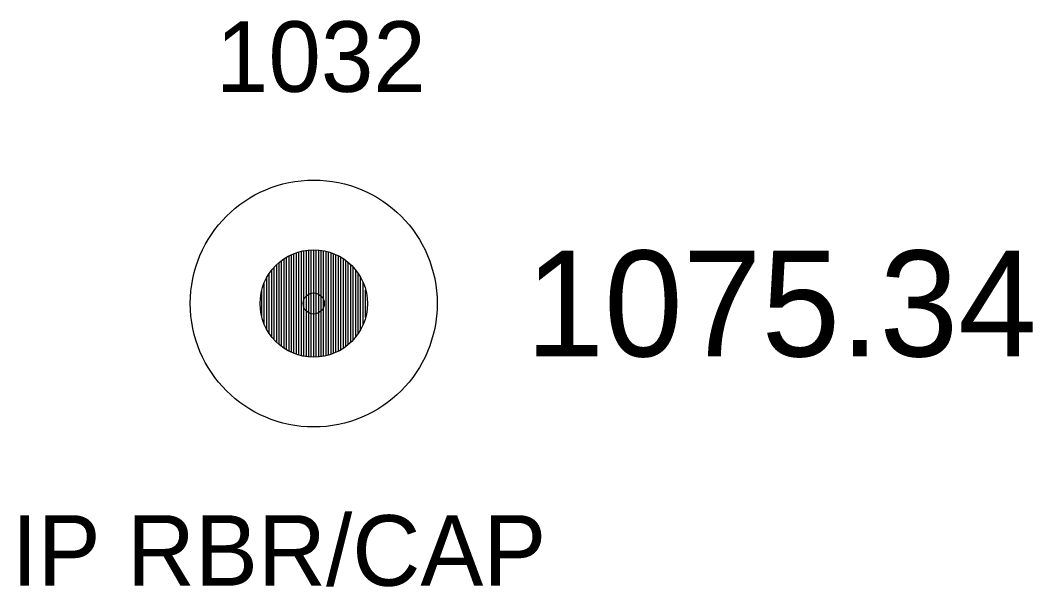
# Model space of a CAD drawing. Extents: x 1578957 to 1581675, y 1115963 to 1120391.
# Drawn here: x 1580946.4 to 1580960.75, y 1119460.76 to 1119468.79 of the extents above; entities that cross this region are included whole.
import ezdxf

# ---------------------------------------------------------------- set-up
doc = ezdxf.new("R2010")
doc.units = 0
for name, color, linetype in [('RD_EX_DV_Prop_txCode', 7, 'Continuous'), ('RD_EX_DV_PropPin', 7, 'Continuous'), ('RD_EX_TX_DV_Prop_ELEV', 7, 'Continuous'), ('RD_SMD_Locator', 7, 'Continuous')]:
    doc.layers.add(name, color=color, linetype=linetype)

msp = doc.modelspace()

# ---------------------------------------------------------------- linework, layer by layer
at = {"layer": 'RD_EX_DV_PropPin'}
for p, q in [((1580950.243, 1119464.083), (1580950.243, 1119465.469)), ((1580950.278, 1119464.068), (1580950.278, 1119465.483)), ((1580950.313, 1119464.055), (1580950.313, 1119465.496)), ((1580950.348, 1119464.044), (1580950.348, 1119465.507)), ((1580950.383, 1119464.035), (1580950.383, 1119465.516)), ((1580950.418, 1119464.028), (1580950.418, 1119465.524)), ((1580950.453, 1119464.022), (1580950.453, 1119465.53)), ((1580950.488, 1119464.018), (1580950.488, 1119465.534)), ((1580950.523, 1119464.016), (1580950.523, 1119465.536)), ((1580950.558, 1119464.015), (1580950.558, 1119465.537)), ((1580950.593, 1119464.016), (1580950.593, 1119465.536)), ((1580950.628, 1119464.018), (1580950.628, 1119465.534)), ((1580950.663, 1119464.022), (1580950.663, 1119465.53)), ((1580950.698, 1119464.028), (1580950.698, 1119465.524)), ((1580950.733, 1119464.035), (1580950.733, 1119465.516)), ((1580950.768, 1119464.044), (1580950.768, 1119465.507)), ((1580950.803, 1119464.055), (1580950.803, 1119465.496)), ((1580950.838, 1119464.068), (1580950.838, 1119465.483)), ((1580950.873, 1119464.083), (1580950.873, 1119465.469)), ((1580950.033, 1119464.225), (1580950.033, 1119465.327)), ((1580950.068, 1119464.194), (1580950.068, 1119465.358)), ((1580950.103, 1119464.166), (1580950.103, 1119465.386)), ((1580950.138, 1119464.141), (1580950.138, 1119465.41)), ((1580950.173, 1119464.119), (1580950.173, 1119465.432)), ((1580950.208, 1119464.1), (1580950.208, 1119465.451)), ((1580950.908, 1119464.1), (1580950.908, 1119465.451)), ((1580950.943, 1119464.119), (1580950.943, 1119465.432)), ((1580950.978, 1119464.141), (1580950.978, 1119465.41)), ((1580951.013, 1119464.166), (1580951.013, 1119465.386)), ((1580951.048, 1119464.194), (1580951.048, 1119465.358)), ((1580951.083, 1119464.225), (1580951.083, 1119465.327)), ((1580949.928, 1119464.349), (1580949.928, 1119465.202)), ((1580949.963, 1119464.302), (1580949.963, 1119465.25)), ((1580949.998, 1119464.261), (1580949.998, 1119465.291)), ((1580951.118, 1119464.261), (1580951.118, 1119465.291)), ((1580951.153, 1119464.302), (1580951.153, 1119465.25)), ((1580951.188, 1119464.349), (1580951.188, 1119465.202)), ((1580949.857, 1119464.478), (1580949.857, 1119465.074)), ((1580949.893, 1119464.406), (1580949.893, 1119465.145)), ((1580951.223, 1119464.406), (1580951.223, 1119465.145)), ((1580951.258, 1119464.478), (1580951.258, 1119465.074)), ((1580949.822, 1119464.58), (1580949.822, 1119464.972)), ((1580951.293, 1119464.58), (1580951.293, 1119464.972))]:
    msp.add_line(p, q, dxfattribs=at)
for radius in [1.75, 0.761]:
    msp.add_circle((1580950.558, 1119464.776), radius, dxfattribs=at)
at = {"layer": 'RD_SMD_Locator'}
msp.add_circle((1580950.558, 1119464.776), 0.15, dxfattribs=at)

# ---------------------------------------------------------------- texts
at = {"layer": 'RD_EX_DV_Prop_txCode'}
for s, p in [('1032', (1580949.172, 1119467.776)), ('IP RBR/CAP', (1580946.274, 1119460.776))]:
    msp.add_text(s, height=1, dxfattribs=at).set_placement(p)
at = {"layer": 'RD_EX_TX_DV_Prop_ELEV'}
msp.add_text('1075.34', height=1.5, dxfattribs=at).set_placement((1580953.558, 1119464.026))

doc.saveas('drawing.dxf')
